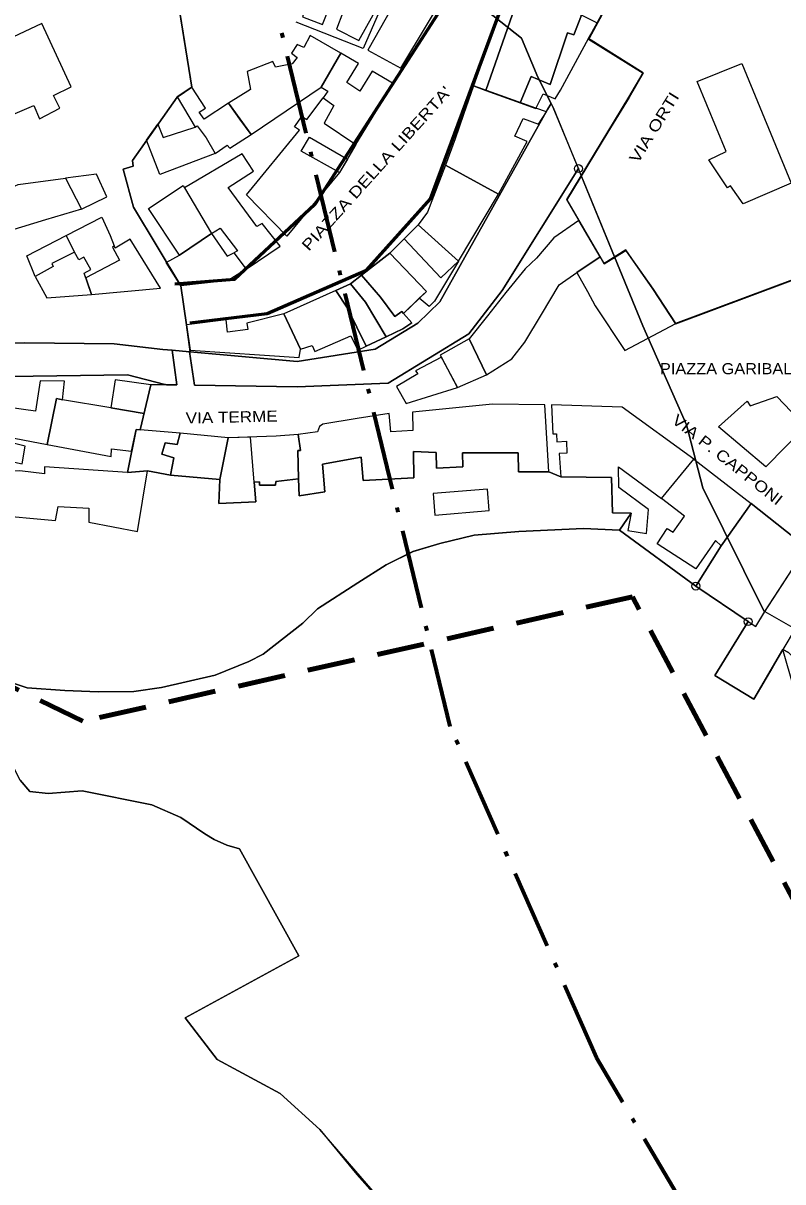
# Model space of a CAD drawing. Extents: x 654952 to 658955, y 890426 to 894481.
# Drawn here: x 657969.7 to 658161.5, y 890856.2 to 891148.5 of the extents above; entities that cross this region are included whole.
import ezdxf

# ---------------------------------------------------------------- set-up
doc = ezdxf.new("R2010")
doc.units = 0
doc.header["$LTSCALE"] = 4
doc.header["$PDMODE"] = 32
doc.header["$PDSIZE"] = 2
doc.linetypes.add('DOT_DASHED', pattern=[7.7, 5, -1.2, 0.3, -1.2])
doc.linetypes.add('MEDIUM_DASHED', pattern=[4.5, 3, -1.5])
for name, color, linetype, lineweight in [('1', 7, 'Continuous', 25), ('35', 7, 'Continuous', 25), ('4', 7, 'Continuous', 25), ('40', 7, 'Continuous', 60), ('45', 7, 'Continuous', 25), ('55', 7, 'Continuous', 25), ('7', 7, 'MEDIUM_DASHED', 100), ('8', 7, 'Continuous', 25)]:
    doc.layers.add(name, color=color, linetype=linetype, lineweight=lineweight)
doc.layers.add('58', color=7, linetype='Continuous')

msp = doc.modelspace()

# ---------------------------------------------------------------- linework, layer by layer
at = {"layer": '1'}
for p, q in [((658139.53, 891006.49), (658152.75, 890997.52)), ((658152.75, 890997.52), (658144.37, 890983.94))]:
    msp.add_line(p, q, dxfattribs=at)
for points in [[(658103.03, 891128.29), (658099.62, 891134.92), (658095.53, 891144.7), (658064.96, 891168.92), (658051.77, 891201.3), (658050.19, 891196.98), (658047.85, 891197.98), (658045.52, 891182.46)], [(658181.48, 891090.36), (658134.43, 891072.77), (658128.69, 891081.52), (658121.85, 891091.3), (658116.36, 891087.89), (658115.35, 891089.62), (658106.95, 891104.02), (658117.31, 891121.09), (658122.66, 891129.89), (658126.23, 891136.01), (658112.4, 891144.62), (658114.64, 891148.62), (658112.63, 891144.93), (658119.46, 891157.53), (658122.39, 891162.92), (658112.53, 891167.62), (658108.97, 891169.32), (658105.21, 891170.8), (658101.73, 891172.17), (658097.66, 891173.47)], [(658006.72, 891167.02), (658012.28, 891132.38), (658008.65, 891129.88), (657997.35, 891113.85), (657997.53, 891112.42), (657995.02, 891111.66), (657997.56, 891102.12), (658009.55, 891082.21)], [(658009.55, 891082.21), (657997.56, 891102.12), (657995.02, 891111.66), (657997.53, 891112.42), (657997.35, 891113.85), (658008.65, 891129.88), (658012.28, 891132.38), (658006.73, 891166.96)], [(658119.5, 891157.43), (658112.67, 891144.83), (658114.68, 891148.52), (658112.44, 891144.52), (658126.27, 891135.91), (658122.7, 891129.79), (658117.35, 891120.99), (658106.99, 891103.92), (658115.39, 891089.52), (658116.4, 891087.79), (658121.89, 891091.2), (658128.73, 891081.42), (658134.47, 891072.67), (658181.52, 891090.26), (658218.54, 891002.58), (658195.38, 890993.42), (658184.51, 891003.86), (658180.37, 891008.29), (658170.47, 891014.21), (658166.6, 891016.69), (658164.47, 891018.68), (658153.51, 891027.33), (658145.94, 891016.68), (658139.53, 891006.49)], [(658011.88, 891065.59), (658038.91, 891063.16), (658058.62, 891066.3), (658069.33, 891072.84), (658074.94, 891078.19), (658102.06, 891126.71), (658103.03, 891128.29)], [(658109.89, 891111.84), (658090.61, 891081.07), (658082.26, 891070.1), (658061.89, 891057.68), (658038.91, 891056.76), (658012.98, 891057.17), (658011.76, 891065.61)], [(658119.04, 891089.55), (658110.62, 891110.06), (658109.89, 891111.84)], [(658156.84, 890999.94), (658141.29, 891031.32), (658137.14, 891047.22), (658126.17, 891072.18), (658119.04, 891089.55)], [(658009.55, 891082.21), (658011, 891072.41), (658011.88, 891065.59)], [(658011.88, 891065.59), (658011, 891072.41), (658009.55, 891082.21)], [(658007.35, 891066), (658005, 891066.21), (657992.69, 891067.61), (657970.1, 891067.87), (657935.78, 891067.08), (657921.68, 891064.73), (657916.45, 891061.72)], [(657916.45, 891061.72), (657921.68, 891064.73), (657935.78, 891067.08), (657970.1, 891067.87), (657992.69, 891067.61), (658005, 891066.21), (658007.35, 891066), (658011.76, 891065.61), (658011.88, 891065.59)], [(658005.67, 891057.34), (658005.88, 891057.28), (658008.55, 891057.24), (658007.35, 891066)], [(658011.76, 891065.61), (658007.35, 891066), (658008.55, 891057.24)], [(658005.48, 891057.35), (657996.08, 891059.77), (657960.31, 891059.25), (657940.21, 891058.85), (657927.42, 891057.15), (657901.7, 891050.1), (657878.59, 891038.73), (657852.74, 891026.46), (657852.37, 891025.82), (657837.96, 891005.1), (657836.03, 890997.85)], [(657927.42, 891057.15), (657940.21, 891058.85), (657960.31, 891059.25), (657996.08, 891059.77), (658005.48, 891057.35), (658005.67, 891057.34)], [(657999.3, 891045.92), (658001.99, 891057.24), (658005.48, 891057.35)], [(658005.67, 891057.34), (658005.48, 891057.35), (658001.99, 891057.24), (657999.3, 891045.92)], [(658008.55, 891057.24), (658005.88, 891057.28), (658005.67, 891057.34)], [(658080.75, 891036.56), (658074.03, 891036.28), (658073.96, 891040.2), (658068.23, 891040.42), (658068.38, 891033.82), (658055.53, 891033.1), (658055.07, 891039), (658045.26, 891037.28), (658045.89, 891030.24), (658039.42, 891029.3), (658039.22, 891033.52), (658033.51, 891032.92), (658033.45, 891031.98), (658029.42, 891031.92), (658029.37, 891032.8), (658028.04, 891032.72), (658028.45, 891027.78), (658019.09, 891027.32), (658019.34, 891033.36), (658006.93, 891034.48), (658001.09, 891035.58), (657996.11, 891035.12), (657998.22, 891046.04), (657999.3, 891045.92)], [(657999.3, 891045.92), (657998.22, 891046.04), (657996.11, 891035.12), (658001.09, 891035.58), (658006.93, 891034.48), (658019.34, 891033.36), (658019.09, 891027.32), (658028.45, 891027.78), (658028.04, 891032.72), (658029.37, 891032.8), (658029.42, 891031.92), (658033.45, 891031.98), (658033.51, 891032.92), (658039.22, 891033.52), (658039.42, 891029.3), (658045.89, 891030.24), (658045.26, 891037.28), (658055.07, 891039), (658055.53, 891033.1), (658068.38, 891033.82), (658068.23, 891040.42), (658073.96, 891040.2), (658074.03, 891036.28), (658080.75, 891036.56)], [(658120.29, 891020.64), (658123.2, 891024.86), (658118.46, 891024.98), (658118.27, 891033.86), (658105.46, 891034.04), (658102.42, 891035.3), (658094.77, 891035.32), (658094.66, 891040.08), (658080.66, 891040.08), (658080.75, 891036.56)], [(658080.75, 891036.56), (658080.66, 891040.08), (658094.66, 891040.08), (658094.77, 891035.32), (658102.42, 891035.3), (658105.46, 891034.04), (658118.27, 891033.86), (658118.46, 891024.98), (658123.2, 891024.86), (658120.29, 891020.64), (658139.53, 891006.49), (658152.75, 890997.52)], [(657965.69, 890982.49), (657970.77, 890980.82), (657980.25, 890980.13), (657988.68, 890979.78), (657997.63, 890979.87), (658004.69, 890980.9), (658018.19, 890983.99), (658026.74, 890987.47), (658030.34, 890989.35), (658040.35, 890997.16), (658044.04, 891000.74), (658054.19, 891007.35), (658061.37, 891011.86), (658068.14, 891015.2), (658074.92, 891017.25), (658083.59, 891019.31), (658094.85, 891020.31), (658111.16, 891021.02), (658120.29, 891020.64), (658139.53, 891006.49), (658145.94, 891016.68), (658153.51, 891027.33), (658164.47, 891018.68)], [(657970.77, 890980.82), (657980.24, 890980.13), (657988.68, 890979.78), (657997.63, 890979.87), (658004.69, 890980.9), (658018.19, 890983.99), (658026.74, 890987.47), (658030.34, 890989.35), (658040.35, 890997.16), (658044.03, 891000.74), (658054.19, 891007.35), (658061.36, 891011.86), (658068.14, 891015.2), (658074.92, 891017.25), (658083.59, 891019.31), (658094.84, 891020.31), (658111.16, 891021.02), (658120.29, 891020.64)], [(657935.76, 891007.24), (657941.25, 891001.37), (657942.82, 890999.28), (657951.45, 890991.3), (657960.64, 890985.14), (657965.69, 890982.49), (657970.77, 890980.82)], [(658152.75, 890997.52), (658154.72, 890996.26), (658156.84, 890999.94)], [(658144.37, 890983.94), (658154.14, 890977.98), (658161.52, 890990.5), (658162.91, 890989.74), (658177.71, 890975.4), (658182.65, 890970.82), (658190.16, 890960.7), (658196.63, 890954.23), (658203.08, 890947.87), (658204.42, 890945.86), (658205.72, 890943.95), (658214.64, 890926.33)]]:
    msp.add_lwpolyline(points, dxfattribs=at)
msp.add_lwpolyline([(658188.7, 891047.62), (658205.74, 891007.88), (658195, 891003.64), (658189.34, 891008.18), (658184.51, 891003.86), (658195.38, 890993.42), (658186.69, 890984.36), (658177.71, 890975.4), (658162.91, 890989.74), (658161.52, 890990.5), (658154.14, 890977.98), (658144.37, 890983.94), (658152.75, 890997.52), (658154.72, 890996.26), (658156.93, 891000.08), (658167.45, 891016.27), (658180.17, 891029.32), (658175.08, 891042.1)], close=True, dxfattribs=at)
for p in [(658139.53, 891006.49), (658152.75, 890997.52)]:
    msp.add_point(p, dxfattribs=at)
at = {"layer": '35'}
for points in [[(658139.53, 891006.49), (658120.29, 891020.64), (658111.16, 891021.02), (658094.84, 891020.31), (658083.59, 891019.31), (658074.91, 891017.25), (658068.13, 891015.2), (658061.36, 891011.86), (658054.19, 891007.35), (658044.03, 891000.74), (658040.35, 890997.16), (658030.34, 890989.35), (658026.74, 890987.47), (658018.19, 890983.99), (658004.69, 890980.9), (657997.63, 890979.87), (657988.68, 890979.78), (657980.24, 890980.13), (657970.76, 890980.82), (657965.68, 890982.49)], [(658177.27, 890722.55), (658145.37, 890749.45), (658093.46, 890800.73), (658072.44, 890837.18), (658044.62, 890869.41), (658034.59, 890878.44), (658018.74, 890887.07), (658010.62, 890897.55), (658039.33, 890913.23), (658024.33, 890940.23), (658021.17, 890941.12), (658017.98, 890942.57), (658015.6, 890943.95), (658009.52, 890948.14), (658002.18, 890951.3), (657984.65, 890954.87), (657976.07, 890954.2), (657971.42, 890954.68), (657968.98, 890957.5), (657957.76, 890979.29), (657951.45, 890991.3), (657942.82, 890999.28), (657941.25, 891001.37), (657935.76, 891007.24)], [(658213.99, 890867.74), (658185.33, 890926.17), (658173.89, 890943.74), (658167.04, 890971.14), (658161.52, 890990.5), (658154.14, 890977.98), (658144.37, 890983.94), (658152.75, 890997.52), (658139.53, 891006.49)], [(657968.98, 890957.5), (657971.42, 890954.68), (657976.07, 890954.2), (657984.65, 890954.87), (658002.18, 890951.3), (658009.52, 890948.14), (658015.6, 890943.95), (658017.98, 890942.57), (658021.17, 890941.12), (658024.33, 890940.23), (658039.33, 890913.23), (658010.62, 890897.55), (658018.74, 890887.07), (658034.59, 890878.44), (658044.62, 890869.41)], [(658044.62, 890869.41), (658053.99, 890858.05), (658072.44, 890837.18), (658093.46, 890800.73), (658145.37, 890749.45), (658177.27, 890722.55), (658209.51, 890698.32), (658217.94, 890689.89), (658221.35, 890685.08), (658227.97, 890672.83), (658235.17, 890655.67), (658250.77, 890626.38), (658261.33, 890621.22), (658389.5, 890571.65), (658439.45, 890554.58)]]:
    msp.add_lwpolyline(points, dxfattribs=at)
at = {"layer": '4'}
for points in [[(658060.65, 891179.62), (658052.96, 891160.66), (658038.23, 891166.46), (658035.63, 891160.34), (658042.58, 891157.4), (658040.22, 891150.1), (658045.26, 891148.22), (658047.04, 891152.62), (658050.44, 891151.18), (658048.84, 891147), (658054.43, 891144.14), (658061.32, 891156.46), (658064.23, 891154.96), (658056.73, 891141.74), (658065.07, 891137.18), (658085.54, 891171.24), (658078.05, 891175.56), (658072.91, 891166.42), (658069.35, 891168.24), (658072.91, 891175.24)], [(658095.06, 891155.92), (658092.04, 891156.97), (658083.37, 891132.7), (658086.52, 891131.53)], [(658095.06, 891155.92), (658086.52, 891131.53), (658095.23, 891128.41), (658098, 891135.1), (658102.74, 891133.01), (658107.11, 891146.12), (658108.72, 891145.59), (658110.65, 891150.5)], [(658110.67, 891150.54), (658108.72, 891145.59), (658107.11, 891146.12), (658102.74, 891133.01), (658098, 891135.1), (658095.23, 891128.41), (658099.18, 891127), (658100.99, 891130.66), (658104, 891129.44), (658105.41, 891131.62), (658112.4, 891144.62), (658114.68, 891148.52)], [(658021.6, 891128.3), (658027.32, 891120.4), (658044.95, 891132.38), (658049.92, 891140.96), (658042.22, 891145.42), (658040.55, 891142.36), (658038.89, 891143.12), (658037.44, 891140.96), (658038.88, 891139.84), (658037.66, 891138.24), (658033.47, 891137.44), (658032.72, 891138.82), (658026.24, 891136.36), (658027.11, 891131.82)], [(658045.69, 891123.26), (658053.72, 891117.92), (658063.1, 891133.34), (658057.81, 891136.4), (658054.72, 891131.36), (658051.44, 891133.56), (658054.38, 891138.38), (658049.92, 891140.96), (658044.95, 891132.38), (658046.68, 891131.36), (658045.44, 891129.68), (658048.15, 891127.74)], [(658139.9, 891133.78), (658151.14, 891138.38), (658163.6, 891108.18), (658151.49, 891102.96), (658148.28, 891107.46), (658147.53, 891107), (658142.82, 891114.02), (658147.18, 891116.12)], [(658008.63, 891129.94), (658013.16, 891122.3), (658013.66, 891122.62), (658015.97, 891119.58), (658018.16, 891115.62), (658021.25, 891117.76), (658021.92, 891117.02), (658027.32, 891120.4), (658024.46, 891124.34), (658021.6, 891128.3), (658015.43, 891124.34), (658014.15, 891126.06), (658015.73, 891127.08), (658012.28, 891132.38)], [(658076.37, 891112.66), (658089.7, 891105.4), (658096.99, 891118.64), (658093.84, 891119.98), (658095.93, 891124.5), (658099.8, 891123), (658101.81, 891126.12), (658099.16, 891127.06), (658083.37, 891132.7), (658080.88, 891125.48), (658078.76, 891119.32)], [(658053.72, 891117.92), (658049.62, 891110.88), (658036.31, 891094.74), (658026.07, 891105.24), (658039.5, 891121.52), (658038.22, 891122.4), (658040.05, 891124.94), (658041.38, 891124.22), (658045.44, 891129.68), (658048.15, 891127.74), (658045.69, 891123.26)], [(658000.91, 891119.04), (658003.71, 891123.06), (658005.11, 891119.68), (658013.16, 891122.3), (658013.66, 891122.62), (658015.97, 891119.58), (658018.16, 891115.62), (658004.27, 891110.3)], [(658049.62, 891110.88), (658039.95, 891116.24), (658042.03, 891119.8), (658051.58, 891114.24)], [(658024.98, 891115.58), (658010.5, 891106.94), (658017.29, 891095.44), (658019.47, 891096.8), (658023.87, 891091.08), (658022.91, 891090.6), (658026.01, 891086.44), (658034.63, 891092.22), (658030.08, 891097.94), (658028.69, 891097.22), (658021.52, 891107.06), (658027.89, 891111.2)], [(658069.44, 891097.64), (658079.61, 891088.5), (658089.7, 891105.4), (658076.37, 891112.66), (658071.84, 891100.84)], [(657964.67, 891106.16), (657968.48, 891107.8), (657980.46, 891109.4), (657984.44, 891101.62), (657975.36, 891098.88), (657966.28, 891096.14)], [(657980.46, 891109.4), (657984.44, 891101.62), (657990.87, 891104.74), (657988.26, 891110.44)], [(658009.21, 891089.98), (658001.34, 891101.74), (658010.09, 891107.56), (658010.5, 891106.94), (658017.29, 891095.44)], [(657980.55, 891094.92), (657989.58, 891099.56), (657991.69, 891094.98), (657992.74, 891092.32), (657992.27, 891092.04), (657994.05, 891088.76), (657985.56, 891084.3), (657985.17, 891085.48), (657986.81, 891086.38), (657985.03, 891089.5), (657983.76, 891088.84), (657982.68, 891090.76)], [(658075.18, 891084.3), (658079.61, 891088.5), (658069.44, 891097.64), (658065.88, 891094.08)], [(658082.28, 891068.86), (658086.73, 891059.76), (658093.08, 891063.86), (658096.36, 891068.02), (658100.55, 891075.04), (658105.01, 891082.48), (658109.53, 891085.58), (658115.37, 891089.58), (658110.03, 891098.74), (658103.66, 891094.32), (658099.28, 891089.26), (658096.45, 891086.58), (658091.56, 891080.56), (658086.92, 891074.7)], [(657982.68, 891090.76), (657976.97, 891087.92), (657977.35, 891087.14), (657972.73, 891084.64), (657970.63, 891089.82), (657980.55, 891094.92)], [(657996.78, 891094.06), (657992.94, 891091.78), (657992.74, 891092.32), (657992.27, 891092.04), (657994.05, 891088.76), (657985.56, 891084.3), (657986.98, 891080.06), (658004.39, 891081.68)], [(658017.29, 891095.44), (658021.24, 891089.76), (658022.91, 891090.6), (658026.01, 891086.44), (658021.45, 891083.58), (658009.53, 891082.26), (658005.84, 891088.14), (658009.21, 891089.98)], [(658079.61, 891088.5), (658073.57, 891078.4), (658072.2, 891077), (658069.73, 891079.12), (658071.52, 891080.8), (658062.32, 891090.52), (658065.88, 891094.08), (658075.18, 891084.3)], [(658121.87, 891091.26), (658116.38, 891087.84), (658115.37, 891089.58), (658109.53, 891085.58), (658112.15, 891080.86), (658114.14, 891077.2), (658121.62, 891065.94), (658134.45, 891072.72), (658128.71, 891081.48)], [(657972.73, 891084.64), (657975.68, 891079.26), (657986.98, 891080.06), (657985.17, 891085.48), (657986.81, 891086.38), (657985.03, 891089.5), (657983.76, 891088.84), (657982.68, 891090.76), (657976.97, 891087.92), (657977.35, 891087.14)], [(658056.35, 891067.04), (658051.64, 891076.64), (658048.66, 891081.08), (658052.4, 891082.78), (658055.17, 891084.94), (658062.32, 891090.52), (658071.52, 891080.8), (658069.73, 891079.12), (658065.72, 891075.3), (658067.88, 891072.94), (658065.54, 891071.38), (658061.33, 891069.36)], [(658055.17, 891084.94), (658059.92, 891079.36), (658063.54, 891074.5), (658065.28, 891075.78), (658065.72, 891075.3), (658071.52, 891080.8), (658062.32, 891090.52)], [(658052.4, 891082.78), (658048.66, 891081.08), (658051.64, 891076.64), (658056.35, 891067.04), (658061.33, 891069.36), (658056.16, 891078.1)], [(658055.17, 891084.94), (658052.4, 891082.78), (658056.16, 891078.1), (658061.33, 891069.36), (658065.54, 891071.38), (658067.88, 891072.94), (658065.72, 891075.3), (658065.28, 891075.78), (658063.54, 891074.5), (658059.92, 891079.36)], [(658035.55, 891075.18), (658039.73, 891066.3), (658042.65, 891067.2), (658043.32, 891065.7), (658052.48, 891069.66), (658054.18, 891066.04), (658056.35, 891067.04), (658051.64, 891076.64), (658048.66, 891081.08)], [(658011, 891072.41), (658011.88, 891066.06), (658039.42, 891064.2), (658039.73, 891066.3), (658035.55, 891075.18), (658026.23, 891072.79), (658026.46, 891071.22), (658021.31, 891070.6), (658020.94, 891073.68)], [(658074.96, 891064.74), (658079.4, 891056.58), (658086.73, 891059.76), (658082.28, 891068.86)], [(658075.32, 891064.22), (658068.77, 891060.84), (658069.37, 891060.08), (658064.01, 891056.88), (658066.45, 891052.54), (658072.93, 891054.56), (658079.4, 891056.58)], [(657991.83, 891051.44), (658000.24, 891050.02), (658001.97, 891057.3), (657993, 891058.5)], [(657978.18, 891053.86), (657975.79, 891042.26), (657991.94, 891039.22), (657992.07, 891041.16), (657997.1, 891040.54), (657998.22, 891046.04), (657999.28, 891045.98), (658000.24, 891050.02), (657991.83, 891051.44), (657979.7, 891053.5)], [(658145.28, 891046.64), (658152.46, 891053.12), (658153.29, 891051.96), (658159.94, 891054.32), (658167.25, 891046.8), (658157.21, 891036.62)], [(658094.77, 891035.32), (658102.42, 891035.3), (658101.43, 891052.26), (658088.18, 891052.36), (658067.99, 891050.4), (658068.1, 891045.72), (658062.56, 891045.38), (658062.09, 891050), (658054.05, 891048.82), (658045.34, 891047.32), (658044.56, 891046.74), (658044.06, 891045.4), (658039.13, 891044.78), (658039.76, 891040.68), (658039.08, 891040.68), (658039.22, 891033.52), (658039.42, 891029.3), (658045.89, 891030.24), (658045.26, 891037.28), (658055.07, 891039), (658055.53, 891033.1), (658068.38, 891033.82), (658068.23, 891040.42), (658073.96, 891040.2), (658074.03, 891036.28), (658080.75, 891036.56), (658080.66, 891040.08), (658094.66, 891040.08)], [(658103.06, 891052.22), (658103.45, 891044.92), (658104.38, 891044.9), (658104.48, 891042.9), (658106.9, 891043.04), (658106.93, 891040.06), (658105.04, 891039.98), (658105.46, 891034.04), (658118.27, 891033.86), (658118.46, 891024.98), (658123.2, 891024.86), (658122.39, 891020.48), (658127.09, 891019.74), (658127.61, 891025.82), (658120.1, 891031.36), (658119.98, 891036.56), (658130.86, 891028.58), (658139.02, 891038.54), (658120.9, 891051.64)], [(657998.22, 891046.04), (657996.11, 891035.12), (658001.09, 891035.58), (658006.93, 891034.48), (658007.75, 891038.82), (658004.75, 891039.74), (658005.62, 891042.68), (658008.58, 891042.2), (658009.35, 891045.12)], [(658008.58, 891042.2), (658005.62, 891042.68), (658004.75, 891039.74), (658007.75, 891038.82), (658006.93, 891034.48), (658019.34, 891033.36), (658021.5, 891043.92), (658015.43, 891044.52), (658009.35, 891045.12)], [(658021.5, 891043.92), (658019.34, 891033.36), (658019.09, 891027.32), (658028.45, 891027.78), (658028.04, 891032.72), (658029.37, 891032.8), (658029.42, 891031.92), (658033.45, 891031.98), (658033.51, 891032.92), (658039.22, 891033.52), (658039.08, 891040.68), (658039.76, 891040.68), (658039.13, 891044.78), (658033.56, 891044.28)], [(658021.5, 891043.92), (658019.34, 891033.36), (658019.09, 891027.32), (658028.45, 891027.78), (658028.04, 891032.72), (658027.15, 891044.06)], [(658144.48, 891018.02), (658139.51, 891010.82), (658129.8, 891017.18), (658132.28, 891021), (658133.82, 891020.06), (658136.67, 891024.14), (658130.86, 891028.58), (658139.02, 891038.54), (658153.51, 891027.33), (658145.94, 891016.68)], [(657964.64, 891035.5), (657963.9, 891028.6), (657961.25, 891028.94), (657961.22, 891024.54), (657977.86, 891023.04), (657978.59, 891026.58), (657986.31, 891026.18), (657986.31, 891022.62), (657998.58, 891020.24), (658001.09, 891035.58), (657996.11, 891035.12), (657975.09, 891036.58), (657975.12, 891034.78), (657968.91, 891035.58)], [(658073.19, 891029.84), (658073.64, 891024.4), (658087.37, 891025.54), (658086.93, 891030.98)]]:
    msp.add_lwpolyline(points, close=True, dxfattribs=at)
for points in [[(657961.02, 891122.84), (657972.42, 891127.77), (657973.9, 891124.39), (657978.97, 891127.09), (657977.42, 891130.31), (657981.88, 891132.5), (657974.43, 891148.46), (657974.45, 891148.41), (657954.01, 891138.88)], [(657961.39, 891044), (657960.47, 891039.3), (657969.49, 891037.3), (657970.26, 891041.82), (657965.55, 891043), (657965.71, 891044.16), (657975.79, 891042.26), (657978.18, 891053.86), (657979.7, 891053.5), (657980.21, 891058.22), (657974.02, 891058.3), (657972.83, 891050.64), (657962.47, 891052.04), (657946.14, 891054.22), (657945.08, 891044.58), (657952.05, 891044.46), (657958.41, 891043.84), (657958.41, 891044.52)], [(658158.95, 890986.14), (658154.14, 890977.98), (658144.37, 890983.94), (658152.75, 890997.52)], [(658152.75, 890997.52), (658154.72, 890996.26), (658156.93, 891000.08), (658164.57, 890995.68), (658161.52, 890990.5), (658161.52, 890990.5), (658158.95, 890986.14)]]:
    msp.add_lwpolyline(points, dxfattribs=at)
at = {"layer": '40'}
for points in [[(658047.53, 891586.68), (658065.8, 891564.56), (658072.58, 891488.48), (658078.76, 891414.16), (658085.24, 891320.08), (658094.09, 891213.92), (658080.24, 891159.95), (658043.39, 891102.74), (658023.06, 891083.86), (658008.02, 891082.68)], [(658011.86, 891072.95), (658031.31, 891075.31), (658056.36, 891086.22), (658072.57, 891104.21), (658098.22, 891173.51)]]:
    msp.add_lwpolyline(points, dxfattribs=at)
at = {"layer": '45', "linetype": 'DOT_DASHED', "lineweight": 70}
msp.add_lwpolyline([(658343.4, 890537.48), (658323.23, 890567.38), (658199.11, 890752.18), (658152.38, 890823.25), (658114.5, 890887.55), (658077.53, 890971.09), (658011.97, 891240.99)], dxfattribs=at)
at = {"layer": '55'}
for points in [[(657971.97, 891582.71), (657974.69, 891579.7), (658005.05, 891557.44), (658016.35, 891546.87), (658018.38, 891544.51), (658019.17, 891542.72), (658023.37, 891488.38), (658027.98, 891444.55), (658032.66, 891400.94), (658041.09, 891309.92), (658050.36, 891204.78), (658064.96, 891168.92), (658095.53, 891144.7), (658099.62, 891134.92), (658103.55, 891127.27), (658126.17, 891072.18), (658137.14, 891047.22), (658141.29, 891031.32), (658156.84, 890999.94), (658167.45, 891016.27)], [(658103.03, 891128.29), (658102.06, 891126.71), (658074.94, 891078.19), (658069.33, 891072.84), (658058.62, 891066.3), (658038.91, 891063.16), (658011.88, 891065.59), (658011.76, 891065.61), (658012.98, 891057.17)], [(658109.89, 891111.84), (658103.55, 891127.27), (658103.03, 891128.29)], [(658061.89, 891057.68), (658082.26, 891070.1), (658090.61, 891081.07), (658109.89, 891111.84)], [(658012.98, 891057.17), (658038.91, 891056.76), (658061.89, 891057.68)]]:
    msp.add_lwpolyline(points, dxfattribs=at)
msp.add_point((658109.89, 891111.84), dxfattribs=at)
at = {"layer": '7'}
msp.add_lwpolyline([(658184.33, 890889.29), (658123.56, 891003.8), (657984.81, 890972.39), (657924.04, 891001.78), (657867.48, 890983.79), (657828.91, 890933.62), (657730.13, 890826.94), (657605.09, 890761.67), (657625.78, 890734.22), (657633.49, 890699.48), (657619.39, 890680.55), (657581.42, 890722.64), (657563.43, 890772.81), (657526.14, 890797.25), (657562.14, 890822.34), (657553.14, 890879.58), (657603.92, 890886.02), (657709.35, 890939.4), (657787.21, 890948.05), (657815.02, 890978.31), (657798.98, 891039.09), (657789.02, 891111.62), (657758.18, 891086.01), (657767.85, 891164.67)], dxfattribs=at)
at = {"layer": '8'}
msp.add_lwpolyline([(658061.65, 891156.08), (658055.55, 891142.16), (658038.67, 891148.81)], dxfattribs=at)

# ---------------------------------------------------------------- texts
at = {"layer": '58'}
for s, height, rotation, width, p in [("PIAZZA DELLA LIBERTA'", 2.796, 48.001, 1.25, (658041.86, 891090.81)), ('VIA ORTI', 2.803, 58.215, 1.25, (658124.93, 891112.96)), ('VIA TERME', 2.801, 1.278, 1.15, (658010.8, 891047.49)), ('VIA P. CAPPONI', 2.798, 321.69, 1.2, (658133.24, 891047.88))]:
    msp.add_text(s, height=height, rotation=rotation, dxfattribs=dict(at, width=width)).set_placement(p)
at = {"layer": '58', "width": 1.1}
msp.add_text('PIAZZA GARIBALDI', height=2.801, dxfattribs=at).set_placement((658130.47, 891059.95))

doc.saveas('drawing.dxf')
